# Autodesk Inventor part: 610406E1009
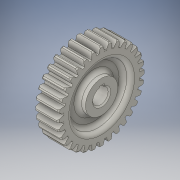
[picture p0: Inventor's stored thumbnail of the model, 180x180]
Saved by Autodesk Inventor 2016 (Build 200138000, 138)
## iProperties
Created: 2021-04
Part Number: 610406E1009
Material: 강철, 가공됨
Document SubType Name: Modeling
Designer: PC-1-3
Density: 7.85 g/cm^3
Appearance: 강철
Mass: 330.109 g
Surface Area: 156.55 cm^2
Volume: 42.0521 cm^3
Author: PC-1-3
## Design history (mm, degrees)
sketch "스케치1"
  geometry: L1 (-9, 0)-(9, 0); L2 (-9, 6)-(9, 6); L3 (9, 6)-(9, 12.5); L4 (9, 12.5)-(3, 12.5); L5 (3, 12.5)-(3, 22.5); L6 (3, 22.5)-(9, 22.5); L7 (9, 22.5)-(9, 29.5); L8 (9, 29.5)-(-9, 29.5); L9 (-9, 29.5)-(-9, 22.5); L10 (-9, 22.5)-(-3, 22.5); L11 (-3, 22.5)-(-3, 12.5); L12 (-3, 12.5)-(-9, 12.5); L13 (-9, 6)-(-9, 12.5); 2 further points
  constraints: 26 end point, 8 perpendicular, 7 point on line, 2 horizontal, 2 vertical alignment, 1 coincident, 1 midpoint
  dimensions: "d0" = 18 distance of L1.start L1.end; "d1" = 12 diameter of L2 L1; "d2" = 25 diameter of L12 L1; "d3" = 45 diameter of L10 L1; "d4" = 59 diameter of L8 L1; "d5" = 6 distance between parallel lines of L5 L11; "d6" = 6 distance between parallel lines of L11 L9
revolve "회전1" sketch "스케치1" stored, may be unused: angle "d7" = 90 deg
sketch "스케치3"
  geometry: L1 (-2, 5.657)-(-2, 7.8); L2 (-2, 7.8)-(2, 7.8); L3 (2, 7.8)-(2, 5.657); A1 r 6 centre (0, 0) between (-2, 5.657) and (2, 5.657) reference; 1 further point
  constraints: 6 end point, 2 perpendicular, 2 point on circle, 1 parallel, 1 vertical
  dimensions: "d8" = 13.8 dimension on A1 L2; "d9" = 4 distance of L1.end L2.end
extrude "돌출1" cut sketch "스케치3" stored distance "d10" = 10; taper "d11" = 0 deg
sketch "스케치4"
  geometry: L1 (0, 0)-(0, 34); L2 (-0.57, 29.494)-(-0.57, 33.995); L3 (-1.57, 29.458)-(-1.57, 33.964); L4 (-2.07, 29.427)-(-2.07, 33.937); C1 r 32 at (0, 0); C2 r 22.5 at (0, 0) reference; A1 r 34 centre (0, 0) between (0, 34) and (-0.57, 33.995); A2 r 29.5 centre (0, 0) between (-0.57, 29.494) and (-1.57, 29.458) reference; A3 r 9.275 centre (7.191, 28.917) between (-0.57, 33.995) and (-2.07, 29.427); A4 r 9.275 centre (-7.191, 28.917) between (2.07, 29.427) and (0.57, 33.995); A5 r 29.5 centre (0, 0) between (2.07, 29.427) and (-2.07, 29.427); A6 r 34 centre (0, 0) between (0.57, 33.995) and (-0.57, 33.995); 1 further point
  constraints: 15 point on circle, 8 end point, 6 centre point, 4 coincident, 4 vertical, 3 symmetric about line, 1 other
  dimensions: "d12" = 64 diameter of C1; "d13" = 68 diameter of A1; "d14" = 1.57 distance between parallel lines of L3 L1; "d15" = 1 distance between parallel lines of L2 L3; "d16" = 0.5 distance between parallel lines of L3 L4
extrude "돌출2" join sketch "스케치4" stored distance "d17" = 10; taper "d18" = 0 deg
chamfer "모따기1" distance "d19" = 1; stored, may be unused: second distance "d20" = 2, angle "d21" = 45 deg
fillet "모깎기1" dims "d25" = 3
chamfer "모따기2" distance "d26" = 1; stored, may be unused: second distance "d27" = 2, angle "d28" = 45 deg
node "솔리드1"
pattern_circular "원형 패턴1" dims angle "d23" = 360 deg
node "투영된 루프1"
